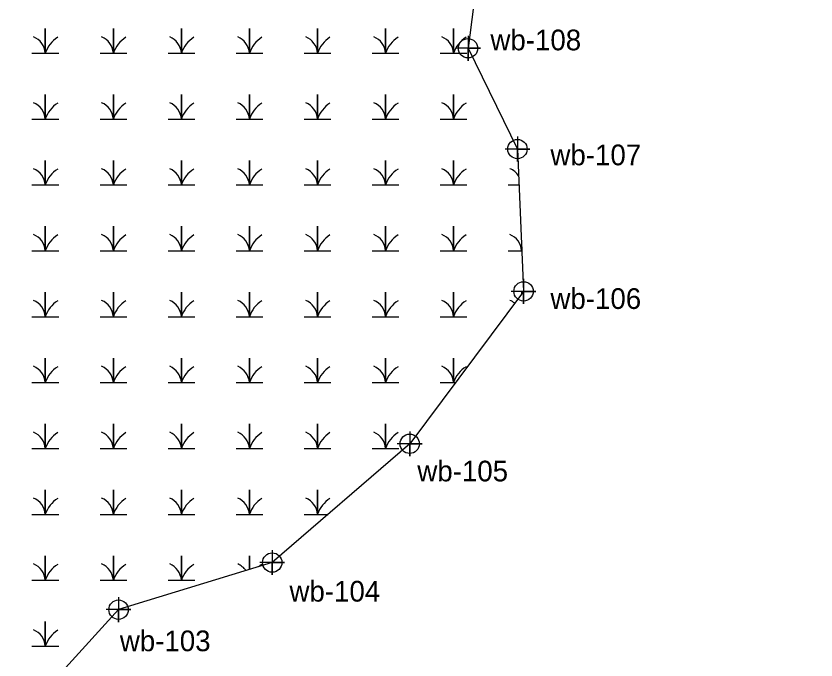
# Model space of a CAD drawing. Extents: x 2379288 to 2381905, y 330670 to 333511.
# Drawn here: x 2380290.9 to 2380484.3, y 332373.5 to 332529.1 of the extents above; entities that cross this region are included whole.
import ezdxf

# ---------------------------------------------------------------- set-up
doc = ezdxf.new("R2010")
doc.units = 0
for name, color, linetype in [('Exist Environmental Wetland Boundary', 7, 'Continuous'), ('Exist Environmental Wetland Boundary Cogo Number', 7, 'Continuous'), ('Exist Environmental Wetland Boundary Cogo Point CELL', 7, 'Continuous'), ('Exist Hydro Swamp or Marsh', 7, 'Continuous')]:
    doc.layers.add(name, color=color, linetype=linetype)

msp = doc.modelspace()

# ---------------------------------------------------------------- linework, layer by layer
at = {"layer": 'Exist Environmental Wetland Boundary'}
msp.add_lwpolyline([(2380626.94, 332703.59), (2380578.61, 332658.53), (2380538.32, 332619.14), (2380494.95, 332601.64), (2380453.1, 332584.48), (2380406.72, 332572.38), (2380400.16, 332521.26), (2380412.11, 332496.92), (2380413.59, 332462.54), (2380386.06, 332425.71), (2380352.83, 332397.02), (2380315.67, 332385.64), (2380290.84, 332358.39), (2380295.85, 332340.3), (2380332.51, 332311.36), (2380326.97, 332300.58), (2380311.82, 332307.72), (2380244.82, 332322.56), (2380185.2, 332357.15), (2380173.71, 332371.44)], dxfattribs=at)
at = {"layer": 'Exist Environmental Wetland Boundary Cogo Point CELL'}
for points in [[(2380400.16, 332524.26), (2380400.16, 332518.26), (2380400.16, 332521.26), (2380403.16, 332521.26), (2380397.16, 332521.26)], [(2380412.11, 332499.92), (2380412.11, 332493.92), (2380412.11, 332496.92), (2380415.11, 332496.92), (2380409.11, 332496.92)], [(2380413.59, 332465.54), (2380413.59, 332459.54), (2380413.59, 332462.54), (2380416.59, 332462.54), (2380410.59, 332462.54)], [(2380386.06, 332428.71), (2380386.06, 332422.71), (2380386.06, 332425.71), (2380389.06, 332425.71), (2380383.06, 332425.71)], [(2380352.83, 332400.02), (2380352.83, 332394.02), (2380352.83, 332397.02), (2380355.83, 332397.02), (2380349.83, 332397.02)], [(2380315.67, 332388.64), (2380315.67, 332382.64), (2380315.67, 332385.64), (2380318.67, 332385.64), (2380312.67, 332385.64)]]:
    msp.add_lwpolyline(points, dxfattribs=at)
for centre in [(2380400.16, 332521.26), (2380412.11, 332496.92), (2380413.59, 332462.54), (2380386.06, 332425.71), (2380352.83, 332397.02), (2380315.67, 332385.64)]:
    msp.add_circle(centre, 2.34, dxfattribs=at)
at = {"layer": 'Exist Hydro Swamp or Marsh'}
msp.add_line((2380409.9, 332488.26), (2380412.49, 332488.26), dxfattribs=at)
for points in [[(2380294.74, 332520.09), (2380297.97, 332520.09), (2380297.97, 332526.01), (2380297.97, 332520.09), (2380301.2, 332520.09)], [(2380311.2, 332520.09), (2380314.42, 332520.09), (2380314.42, 332526.01), (2380314.42, 332520.09), (2380317.65, 332520.09)], [(2380327.65, 332520.09), (2380330.87, 332520.09), (2380330.87, 332526.01), (2380330.87, 332520.09), (2380334.1, 332520.09)], [(2380344.1, 332520.09), (2380347.32, 332520.09), (2380347.32, 332526.01), (2380347.32, 332520.09), (2380350.55, 332520.09)], [(2380360.55, 332520.09), (2380363.78, 332520.09), (2380363.78, 332526.01), (2380363.78, 332520.09), (2380367, 332520.09)], [(2380377, 332520.09), (2380380.23, 332520.09), (2380380.23, 332526.01), (2380380.23, 332520.09), (2380383.45, 332520.09)], [(2380393.45, 332520.09), (2380396.68, 332520.09), (2380396.68, 332526.01), (2380396.68, 332520.09), (2380399.9, 332520.09)], [(2380294.74, 332504.17), (2380297.97, 332504.17), (2380297.97, 332510.09), (2380297.97, 332504.17), (2380301.2, 332504.17)], [(2380311.2, 332504.17), (2380314.42, 332504.17), (2380314.42, 332510.09), (2380314.42, 332504.17), (2380317.65, 332504.17)], [(2380327.65, 332504.17), (2380330.87, 332504.17), (2380330.87, 332510.09), (2380330.87, 332504.17), (2380334.1, 332504.17)], [(2380344.1, 332504.17), (2380347.32, 332504.17), (2380347.32, 332510.09), (2380347.32, 332504.17), (2380350.55, 332504.17)], [(2380360.55, 332504.17), (2380363.78, 332504.17), (2380363.78, 332510.09), (2380363.78, 332504.17), (2380367, 332504.17)], [(2380377, 332504.17), (2380380.23, 332504.17), (2380380.23, 332510.09), (2380380.23, 332504.17), (2380383.45, 332504.17)], [(2380393.45, 332504.17), (2380396.68, 332504.17), (2380396.68, 332510.09), (2380396.68, 332504.17), (2380399.9, 332504.17)], [(2380294.74, 332488.26), (2380297.97, 332488.26), (2380297.97, 332494.17), (2380297.97, 332488.26), (2380301.2, 332488.26)], [(2380311.2, 332488.26), (2380314.42, 332488.26), (2380314.42, 332494.17), (2380314.42, 332488.26), (2380317.65, 332488.26)], [(2380327.65, 332488.26), (2380330.87, 332488.26), (2380330.87, 332494.17), (2380330.87, 332488.26), (2380334.1, 332488.26)], [(2380344.1, 332488.26), (2380347.32, 332488.26), (2380347.32, 332494.17), (2380347.32, 332488.26), (2380350.55, 332488.26)], [(2380360.55, 332488.26), (2380363.78, 332488.26), (2380363.78, 332494.17), (2380363.78, 332488.26), (2380367, 332488.26)], [(2380377, 332488.26), (2380380.23, 332488.26), (2380380.23, 332494.17), (2380380.23, 332488.26), (2380383.45, 332488.26)], [(2380393.45, 332488.26), (2380396.68, 332488.26), (2380396.68, 332494.17), (2380396.68, 332488.26), (2380399.9, 332488.26)], [(2380294.74, 332472.34), (2380297.97, 332472.34), (2380297.97, 332478.26), (2380297.97, 332472.34), (2380301.2, 332472.34)], [(2380311.2, 332472.34), (2380314.42, 332472.34), (2380314.42, 332478.26), (2380314.42, 332472.34), (2380317.65, 332472.34)], [(2380327.65, 332472.34), (2380330.87, 332472.34), (2380330.87, 332478.26), (2380330.87, 332472.34), (2380334.1, 332472.34)], [(2380344.1, 332472.34), (2380347.32, 332472.34), (2380347.32, 332478.26), (2380347.32, 332472.34), (2380350.55, 332472.34)], [(2380360.55, 332472.34), (2380363.78, 332472.34), (2380363.78, 332478.26), (2380363.78, 332472.34), (2380367, 332472.34)], [(2380377, 332472.34), (2380380.23, 332472.34), (2380380.23, 332478.26), (2380380.23, 332472.34), (2380383.45, 332472.34)], [(2380393.45, 332472.34), (2380396.68, 332472.34), (2380396.68, 332478.26), (2380396.68, 332472.34), (2380399.9, 332472.34)], [(2380409.9, 332472.34), (2380413.13, 332472.34), (2380413.13, 332473.29)], [(2380413.13, 332473.29), (2380413.13, 332472.34), (2380413.17, 332472.34)], [(2380294.74, 332456.42), (2380297.97, 332456.42), (2380297.97, 332462.34), (2380297.97, 332456.42), (2380301.2, 332456.42)], [(2380311.2, 332456.42), (2380314.42, 332456.42), (2380314.42, 332462.34), (2380314.42, 332456.42), (2380317.65, 332456.42)], [(2380327.65, 332456.42), (2380330.87, 332456.42), (2380330.87, 332462.34), (2380330.87, 332456.42), (2380334.1, 332456.42)], [(2380344.1, 332456.42), (2380347.32, 332456.42), (2380347.32, 332462.34), (2380347.32, 332456.42), (2380350.55, 332456.42)], [(2380360.55, 332456.42), (2380363.78, 332456.42), (2380363.78, 332462.34), (2380363.78, 332456.42), (2380367, 332456.42)], [(2380377, 332456.42), (2380380.23, 332456.42), (2380380.23, 332462.34), (2380380.23, 332456.42), (2380383.45, 332456.42)], [(2380393.45, 332456.42), (2380396.68, 332456.42), (2380396.68, 332462.34), (2380396.68, 332456.42), (2380399.9, 332456.42)], [(2380413.13, 332461.92), (2380413.13, 332462.34), (2380413.13, 332461.92)], [(2380294.74, 332440.5), (2380297.97, 332440.5), (2380297.97, 332446.42), (2380297.97, 332440.5), (2380301.2, 332440.5)], [(2380311.2, 332440.5), (2380314.42, 332440.5), (2380314.42, 332446.42), (2380314.42, 332440.5), (2380317.65, 332440.5)], [(2380327.65, 332440.5), (2380330.87, 332440.5), (2380330.87, 332446.42), (2380330.87, 332440.5), (2380334.1, 332440.5)], [(2380344.1, 332440.5), (2380347.32, 332440.5), (2380347.32, 332446.42), (2380347.32, 332440.5), (2380350.55, 332440.5)], [(2380360.55, 332440.5), (2380363.78, 332440.5), (2380363.78, 332446.42), (2380363.78, 332440.5), (2380367, 332440.5)], [(2380377, 332440.5), (2380380.23, 332440.5), (2380380.23, 332446.42), (2380380.23, 332440.5), (2380383.45, 332440.5)], [(2380393.45, 332440.5), (2380396.68, 332440.5), (2380396.68, 332446.42), (2380396.68, 332440.5), (2380397.12, 332440.5)], [(2380294.74, 332424.59), (2380297.97, 332424.59), (2380297.97, 332430.5), (2380297.97, 332424.59), (2380301.2, 332424.59)], [(2380311.2, 332424.59), (2380314.42, 332424.59), (2380314.42, 332430.5), (2380314.42, 332424.59), (2380317.65, 332424.59)], [(2380327.65, 332424.59), (2380330.87, 332424.59), (2380330.87, 332430.5), (2380330.87, 332424.59), (2380334.1, 332424.59)], [(2380344.1, 332424.59), (2380347.32, 332424.59), (2380347.32, 332430.5), (2380347.32, 332424.59), (2380350.55, 332424.59)], [(2380360.55, 332424.59), (2380363.78, 332424.59), (2380363.78, 332430.5), (2380363.78, 332424.59), (2380367, 332424.59)], [(2380377, 332424.59), (2380380.23, 332424.59), (2380380.23, 332430.5), (2380380.23, 332424.59), (2380383.45, 332424.59)], [(2380294.74, 332408.67), (2380297.97, 332408.67), (2380297.97, 332414.59), (2380297.97, 332408.67), (2380301.2, 332408.67)], [(2380311.2, 332408.67), (2380314.42, 332408.67), (2380314.42, 332414.59), (2380314.42, 332408.67), (2380317.65, 332408.67)], [(2380327.65, 332408.67), (2380330.87, 332408.67), (2380330.87, 332414.59), (2380330.87, 332408.67), (2380334.1, 332408.67)], [(2380344.1, 332408.67), (2380347.32, 332408.67), (2380347.32, 332414.59), (2380347.32, 332408.67), (2380350.55, 332408.67)], [(2380360.55, 332408.67), (2380363.78, 332408.67), (2380363.78, 332414.59), (2380363.78, 332408.67), (2380366.33, 332408.67)], [(2380294.74, 332392.75), (2380297.97, 332392.75), (2380297.97, 332398.67), (2380297.97, 332392.75), (2380301.2, 332392.75)], [(2380311.2, 332392.75), (2380314.42, 332392.75), (2380314.42, 332398.67), (2380314.42, 332392.75), (2380317.65, 332392.75)], [(2380327.65, 332392.75), (2380330.87, 332392.75), (2380330.87, 332398.67), (2380330.87, 332392.75), (2380334.1, 332392.75)], [(2380347.32, 332395.33), (2380347.32, 332398.67), (2380347.32, 332395.33)], [(2380294.74, 332376.83), (2380297.97, 332376.83), (2380297.97, 332382.75), (2380297.97, 332376.83), (2380301.2, 332376.83)]]:
    msp.add_lwpolyline(points, dxfattribs=at)
for centre, radius, start, end in [((2380293.37, 332519.76), 4.61, 4.1403, 67.535), ((2380304.81, 332517.82), 7.21, 122.1274, 161.6222), ((2380309.82, 332519.76), 4.61, 4.1403, 67.535), ((2380321.26, 332517.82), 7.21, 122.1274, 161.6222), ((2380326.27, 332519.76), 4.61, 4.1403, 67.535), ((2380337.71, 332517.82), 7.21, 122.1274, 161.6222), ((2380342.72, 332519.76), 4.61, 4.1403, 67.535), ((2380354.16, 332517.82), 7.21, 122.1274, 161.6222), ((2380359.18, 332519.76), 4.61, 4.1403, 67.535), ((2380370.62, 332517.82), 7.21, 122.1274, 161.6222), ((2380375.63, 332519.76), 4.61, 4.1403, 67.535), ((2380387.07, 332517.82), 7.21, 122.1274, 161.6222), ((2380392.08, 332519.76), 4.61, 4.1403, 67.535), ((2380403.52, 332517.82), 7.21, 122.1274, 161.6222), ((2380293.37, 332503.84), 4.61, 4.1403, 67.535), ((2380309.82, 332503.84), 4.61, 4.1403, 67.535), ((2380326.27, 332503.84), 4.61, 4.1403, 67.535), ((2380342.72, 332503.84), 4.61, 4.1403, 67.535), ((2380359.18, 332503.84), 4.61, 4.1403, 67.535), ((2380375.63, 332503.84), 4.61, 4.1403, 67.535), ((2380392.08, 332503.84), 4.61, 4.1403, 67.535), ((2380304.81, 332501.9), 7.21, 122.1274, 161.6222), ((2380321.26, 332501.9), 7.21, 122.1274, 161.6222), ((2380337.71, 332501.9), 7.21, 122.1274, 161.6222), ((2380354.16, 332501.9), 7.21, 122.1274, 161.6222), ((2380370.62, 332501.9), 7.21, 122.1274, 161.6222), ((2380387.07, 332501.9), 7.21, 122.1274, 161.6222), ((2380403.52, 332501.9), 7.21, 122.1274, 161.6222), ((2380293.37, 332487.92), 4.61, 4.1403, 67.535), ((2380304.81, 332485.98), 7.21, 122.1274, 161.6222), ((2380309.82, 332487.92), 4.61, 4.1403, 67.535), ((2380321.26, 332485.98), 7.21, 122.1274, 161.6222), ((2380326.27, 332487.92), 4.61, 4.1403, 67.535), ((2380337.71, 332485.98), 7.21, 122.1274, 161.6222), ((2380342.72, 332487.92), 4.61, 4.1403, 67.535), ((2380354.16, 332485.98), 7.21, 122.1274, 161.6222), ((2380359.18, 332487.92), 4.61, 4.1403, 67.535), ((2380370.62, 332485.98), 7.21, 122.1274, 161.6222), ((2380375.63, 332487.92), 4.61, 4.1403, 67.535), ((2380387.07, 332485.98), 7.21, 122.1274, 161.6222), ((2380392.08, 332487.92), 4.61, 4.1403, 67.535), ((2380403.52, 332485.98), 7.21, 122.1274, 161.6222), ((2380408.53, 332487.92), 4.61, 33.1148, 67.535), ((2380293.37, 332472.01), 4.61, 4.1403, 67.535), ((2380304.81, 332470.07), 7.21, 122.1274, 161.6222), ((2380309.82, 332472.01), 4.61, 4.1403, 67.535), ((2380321.26, 332470.07), 7.21, 122.1274, 161.6222), ((2380326.27, 332472.01), 4.61, 4.1403, 67.535), ((2380337.71, 332470.07), 7.21, 122.1274, 161.6222), ((2380342.72, 332472.01), 4.61, 4.1403, 67.535), ((2380354.16, 332470.07), 7.21, 122.1274, 161.6222), ((2380359.18, 332472.01), 4.61, 4.1403, 67.535), ((2380370.62, 332470.07), 7.21, 122.1274, 161.6222), ((2380375.63, 332472.01), 4.61, 4.1403, 67.535), ((2380387.07, 332470.07), 7.21, 122.1274, 161.6222), ((2380392.08, 332472.01), 4.61, 4.1403, 67.535), ((2380403.52, 332470.07), 7.21, 122.1274, 161.6222), ((2380408.53, 332472.01), 4.61, 4.1403, 67.535), ((2380419.97, 332470.07), 7.21, 160.7318, 161.6222), ((2380293.37, 332456.09), 4.61, 4.1403, 67.535), ((2380304.81, 332454.15), 7.21, 122.1274, 161.6222), ((2380309.82, 332456.09), 4.61, 4.1403, 67.535), ((2380321.26, 332454.15), 7.21, 122.1274, 161.6222), ((2380326.27, 332456.09), 4.61, 4.1403, 67.535), ((2380337.71, 332454.15), 7.21, 122.1274, 161.6222), ((2380342.72, 332456.09), 4.61, 4.1403, 67.535), ((2380354.16, 332454.15), 7.21, 122.1274, 161.6222), ((2380359.18, 332456.09), 4.61, 4.1403, 67.535), ((2380370.62, 332454.15), 7.21, 122.1274, 161.6222), ((2380375.63, 332456.09), 4.61, 4.1403, 67.535), ((2380387.07, 332454.15), 7.21, 122.1274, 161.6222), ((2380392.08, 332456.09), 4.61, 4.1403, 67.535), ((2380403.52, 332454.15), 7.21, 122.1274, 161.6222), ((2380408.53, 332456.09), 4.61, 50.8405, 67.535), ((2380293.37, 332440.17), 4.61, 4.1403, 67.535), ((2380304.81, 332438.23), 7.21, 122.1274, 161.6222), ((2380309.82, 332440.17), 4.61, 4.1403, 67.535), ((2380321.26, 332438.23), 7.21, 122.1274, 161.6222), ((2380326.27, 332440.17), 4.61, 4.1403, 67.535), ((2380337.71, 332438.23), 7.21, 122.1274, 161.6222), ((2380342.72, 332440.17), 4.61, 4.1403, 67.535), ((2380354.16, 332438.23), 7.21, 122.1274, 161.6222), ((2380359.18, 332440.17), 4.61, 4.1403, 67.535), ((2380370.62, 332438.23), 7.21, 122.1274, 161.6222), ((2380375.63, 332440.17), 4.61, 4.1403, 67.535), ((2380387.07, 332438.23), 7.21, 122.1274, 161.6222), ((2380392.08, 332440.17), 4.61, 4.1403, 67.535), ((2380403.52, 332438.23), 7.21, 122.1274, 161.6222), ((2380293.37, 332424.25), 4.61, 4.1403, 67.535), ((2380304.81, 332422.31), 7.21, 122.1274, 161.6222), ((2380309.82, 332424.25), 4.61, 4.1403, 67.535), ((2380321.26, 332422.31), 7.21, 122.1274, 161.6222), ((2380326.27, 332424.25), 4.61, 4.1403, 67.535), ((2380337.71, 332422.31), 7.21, 122.1274, 161.6222), ((2380342.72, 332424.25), 4.61, 4.1403, 67.535), ((2380354.16, 332422.31), 7.21, 122.1274, 161.6222), ((2380359.18, 332424.25), 4.61, 4.1403, 67.535), ((2380370.62, 332422.31), 7.21, 122.1274, 161.6222), ((2380375.63, 332424.25), 4.61, 4.1403, 67.535), ((2380387.07, 332422.31), 7.21, 122.1274, 161.6222), ((2380293.37, 332408.34), 4.61, 4.1403, 67.535), ((2380304.81, 332406.4), 7.21, 122.1274, 161.6222), ((2380309.82, 332408.34), 4.61, 4.1403, 67.535), ((2380321.26, 332406.4), 7.21, 122.1274, 161.6222), ((2380326.27, 332408.34), 4.61, 4.1403, 67.535), ((2380337.71, 332406.4), 7.21, 122.1274, 161.6222), ((2380342.72, 332408.34), 4.61, 4.1403, 67.535), ((2380354.16, 332406.4), 7.21, 122.1274, 161.6222), ((2380359.18, 332408.34), 4.61, 4.1403, 67.535), ((2380370.62, 332406.4), 7.21, 122.1274, 161.6222), ((2380293.37, 332392.42), 4.61, 4.1403, 67.535), ((2380304.81, 332390.48), 7.21, 122.1274, 161.6222), ((2380309.82, 332392.42), 4.61, 4.1403, 67.535), ((2380321.26, 332390.48), 7.21, 122.1274, 161.6222), ((2380326.27, 332392.42), 4.61, 4.1403, 67.535), ((2380337.71, 332390.48), 7.21, 122.1274, 161.6222), ((2380342.72, 332392.42), 4.61, 35.2329, 67.535), ((2380354.16, 332390.48), 7.21, 122.1274, 129.8092), ((2380293.37, 332376.5), 4.61, 4.1403, 67.535), ((2380304.81, 332374.56), 7.21, 122.1274, 161.6222)]:
    msp.add_arc(centre, radius, start, end, dxfattribs=at)

# ---------------------------------------------------------------- texts
at = {"layer": 'Exist Environmental Wetland Boundary Cogo Number'}
for s, p in [('wb-108', (2380405.58, 332520.77)), ('wb-107', (2380420.09, 332493)), ('wb-106', (2380420.09, 332458.29)), ('wb-105', (2380387.91, 332416.63)), ('wb-104', (2380357, 332387.59)), ('wb-103', (2380315.99, 332375.6))]:
    msp.add_text(s, height=5, dxfattribs=at).set_placement(p)

doc.saveas('drawing.dxf')
